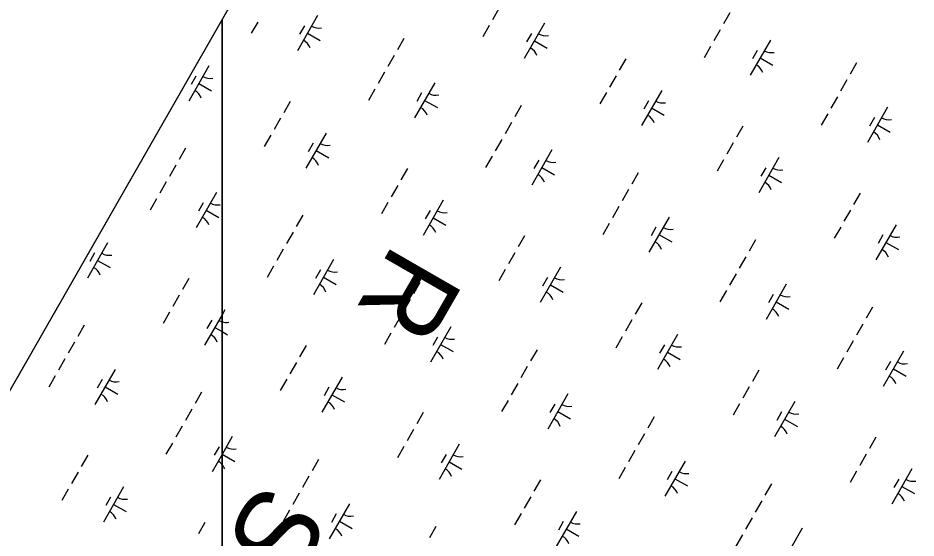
# Model space of a CAD drawing. Extents: x 3930721 to 3950824, y 220441 to 242861.
# Drawn here: x 3937829 to 3938935, y 232817 to 233458 of the extents above; entities that cross this region are included whole.
import ezdxf

# ---------------------------------------------------------------- set-up
doc = ezdxf.new("R2010")
doc.units = 0
for name, color, linetype in [('V-GRID-FRAM', 7, 'Continuous'), ('V-RIVR-IDEN', 7, 'Continuous'), ('V-WETL-SWMP', 7, 'Continuous')]:
    doc.layers.add(name, color=color, linetype=linetype)

msp = doc.modelspace()

# ---------------------------------------------------------------- linework, layer by layer
at = {"layer": 'V-GRID-FRAM'}
msp.add_lwpolyline([(3948829, 235080.9), (3941569.4, 222286.8), (3934009.8, 226348.1), (3941449.6, 239338.6), (3948829, 235080.9)], dxfattribs=at)
at = {"layer": 'V-WETL-SWMP'}
for p, q in [((3938287.6, 233817.5), (3938080.4, 233455.6)), ((3938421.5, 233469.2), (3938413.5, 233455.3)), ((3938706, 233464), (3938698, 233450.2)), ((3938080.4, 233455.6), (3937727.7, 232839.8)), ((3938080.4, 233455.6), (3938080.4, 228590.6)), ((3938080.4, 228590.6), (3938080.4, 233455.6)), ((3938124.4, 233452.6), (3938116.4, 233438.7)), ((3938198.1, 233460.6), (3938173.3, 233417.2)), ((3938182, 233447.9), (3938176, 233437.5)), ((3938409.5, 233448.3), (3938401.6, 233434.4)), ((3938477.7, 233451.1), (3938452.8, 233407.8)), ((3938694, 233443.2), (3938686.1, 233429.3)), ((3938185.7, 233438.9), (3938201.3, 233430)), ((3938304.5, 233432.4), (3938296.6, 233418.5)), ((3938461.5, 233438.5), (3938455.6, 233428.1)), ((3938755.9, 233430.4), (3938731, 233387)), ((3938465.2, 233429.4), (3938480.9, 233420.5)), ((3938682.1, 233422.4), (3938674.2, 233408.5)), ((3938292.6, 233411.6), (3938284.6, 233397.7)), ((3938739.7, 233417.7), (3938733.8, 233407.3)), ((3938743.5, 233408.7), (3938759.1, 233399.7)), ((3938064.3, 233398.7), (3938039.4, 233355.3)), ((3938577.7, 233407.3), (3938569.8, 233393.4)), ((3938862.2, 233402.2), (3938854.3, 233388.3)), ((3938048.1, 233386.1), (3938042.2, 233375.6)), ((3938280.6, 233390.8), (3938272.7, 233376.9)), ((3938565.8, 233386.5), (3938557.9, 233372.6)), ((3938051.8, 233377), (3938067.5, 233368.1)), ((3938342.5, 233377.9), (3938317.6, 233334.5)), ((3938850.3, 233381.4), (3938842.4, 233367.5)), ((3938268.7, 233370), (3938260.8, 233356.1)), ((3938326.3, 233365.3), (3938320.4, 233354.9)), ((3938553.9, 233365.7), (3938545.9, 233351.8)), ((3938622, 233368.5), (3938597.2, 233325.1)), ((3938164.3, 233354.9), (3938156.4, 233341)), ((3938330, 233356.2), (3938345.7, 233347.3)), ((3938605.9, 233355.8), (3938599.9, 233345.4)), ((3938838.4, 233360.5), (3938830.4, 233346.7)), ((3938448.8, 233349.8), (3938440.9, 233335.9)), ((3938609.6, 233346.8), (3938625.2, 233337.8)), ((3938900.2, 233347.7), (3938875.4, 233304.3)), ((3938152.4, 233334.1), (3938144.5, 233320.2)), ((3938826.5, 233339.7), (3938818.5, 233325.8)), ((3938884.1, 233335), (3938878.1, 233324.6)), ((3938436.9, 233328.9), (3938429, 233315.1)), ((3938722.1, 233324.6), (3938714.1, 233310.8)), ((3938887.8, 233326), (3938903.4, 233317.1)), ((3938140.5, 233313.2), (3938132.5, 233299.3)), ((3938208.6, 233316), (3938183.8, 233272.7)), ((3938035.4, 233297.3), (3938027.5, 233283.4)), ((3938192.5, 233303.4), (3938186.5, 233293)), ((3938425, 233308.1), (3938417, 233294.2)), ((3938710.2, 233303.8), (3938702.2, 233289.9)), ((3938196.2, 233294.3), (3938211.8, 233285.4)), ((3938413.1, 233287.3), (3938405.1, 233273.4)), ((3938486.8, 233295.3), (3938462, 233251.9)), ((3938023.5, 233276.5), (3938015.6, 233262.6)), ((3938470.7, 233282.6), (3938464.7, 233272.2)), ((3938698.2, 233283), (3938690.3, 233269.1)), ((3938766.3, 233285.8), (3938741.5, 233242.4)), ((3938308.7, 233272.2), (3938300.7, 233258.3)), ((3938474.4, 233273.6), (3938490, 233264.6)), ((3938593.2, 233267.1), (3938585.2, 233253.2)), ((3938750.2, 233273.2), (3938744.2, 233262.7)), ((3938753.9, 233264.1), (3938769.5, 233255.2)), ((3938011.6, 233255.7), (3938003.6, 233241.8)), ((3938073.4, 233242.8), (3938048.6, 233199.4)), ((3938296.8, 233251.4), (3938288.8, 233237.5)), ((3938581.3, 233246.3), (3938573.3, 233232.4)), ((3938866.4, 233242), (3938858.5, 233228.1)), ((3937999.7, 233234.8), (3937991.7, 233221)), ((3938352.9, 233233.4), (3938328.1, 233190)), ((3938057.3, 233230.2), (3938051.3, 233219.8)), ((3938061, 233221.1), (3938076.6, 233212.2)), ((3938284.8, 233230.6), (3938276.9, 233216.7)), ((3938336.8, 233220.7), (3938330.8, 233210.3)), ((3938569.3, 233225.4), (3938561.4, 233211.6)), ((3938854.5, 233221.2), (3938846.5, 233207.3)), ((3938179.8, 233214.7), (3938171.8, 233200.8)), ((3938340.5, 233211.7), (3938356.1, 233202.7)), ((3938631.2, 233212.6), (3938606.3, 233169.2)), ((3938557.4, 233204.6), (3938549.5, 233190.7)), ((3938615, 233199.9), (3938609.1, 233189.5)), ((3938842.6, 233200.3), (3938834.6, 233186.4)), ((3938910.7, 233203.1), (3938885.8, 233159.8)), ((3938167.9, 233193.8), (3938159.9, 233180)), ((3938453, 233189.5), (3938445.1, 233175.7)), ((3938618.7, 233190.9), (3938634.4, 233182)), ((3938894.6, 233190.5), (3938888.6, 233180.1)), ((3937939.5, 233180.9), (3937914.7, 233137.5)), ((3938737.5, 233184.4), (3938729.6, 233170.5)), ((3938898.3, 233181.4), (3938913.9, 233172.5)), ((3937923.4, 233168.3), (3937917.4, 233157.9)), ((3938155.9, 233173), (3938148, 233159.1)), ((3938441.1, 233168.7), (3938433.1, 233154.8)), ((3937927.1, 233159.2), (3937942.7, 233150.3)), ((3938217.8, 233160.2), (3938192.9, 233116.8)), ((3938725.6, 233163.6), (3938717.6, 233149.7)), ((3938144, 233152.2), (3938136, 233138.3)), ((3938201.6, 233147.5), (3938195.7, 233137.1)), ((3938429.2, 233147.9), (3938421.2, 233134)), ((3938497.3, 233150.7), (3938472.4, 233107.3)), ((3938713.7, 233142.8), (3938705.7, 233128.9)), ((3938039.6, 233137.1), (3938031.7, 233123.2)), ((3938205.3, 233138.5), (3938221, 233129.5)), ((3938324.1, 233132), (3938316.2, 233118.1)), ((3938481.2, 233138.1), (3938475.2, 233127.6)), ((3938484.9, 233129), (3938500.5, 233120.1)), ((3938701.7, 233122), (3938693.8, 233108.1)), ((3938775.5, 233129.9), (3938750.6, 233086.5)), ((3938027.7, 233116.3), (3938019.7, 233102.4)), ((3938312.2, 233111.2), (3938304.2, 233097.3)), ((3938759.4, 233117.3), (3938753.4, 233106.9)), ((3938083.9, 233098.3), (3938080.4, 233092.1)), ((3938597.4, 233106.9), (3938589.4, 233093)), ((3938763.1, 233108.2), (3938778.7, 233099.3)), ((3938881.9, 233101.8), (3938873.9, 233087.9)), ((3938015.8, 233095.5), (3938007.8, 233081.6)), ((3938080.4, 233092.1), (3938059, 233054.9)), ((3938300.3, 233090.3), (3938292.3, 233076.5)), ((3937910.7, 233079.6), (3937902.8, 233065.7)), ((3938067.7, 233085.6), (3938061.8, 233075.2)), ((3938071.5, 233076.6), (3938080.4, 233071.5)), ((3938362.1, 233077.5), (3938337.2, 233034.1)), ((3938585.4, 233086.1), (3938577.5, 233072.2)), ((3938869.9, 233080.9), (3938862, 233067.1)), ((3938080.4, 233071.5), (3938087.1, 233067.6)), ((3938288.3, 233069.5), (3938280.4, 233055.6)), ((3938346, 233064.8), (3938340, 233054.4)), ((3938573.5, 233065.2), (3938565.6, 233051.3)), ((3938641.6, 233068), (3938616.8, 233024.7)), ((3937898.8, 233058.7), (3937890.8, 233044.8)), ((3938184, 233054.4), (3938176, 233040.6)), ((3938349.7, 233055.8), (3938365.3, 233046.9)), ((3938625.5, 233055.4), (3938619.5, 233045)), ((3938858, 233060.1), (3938850.1, 233046.2)), ((3938468.5, 233049.3), (3938460.5, 233035.4)), ((3938629.2, 233046.3), (3938644.8, 233037.4)), ((3938919.8, 233047.3), (3938895, 233003.9)), ((3937886.9, 233037.9), (3937878.9, 233024)), ((3938172, 233033.6), (3938164.1, 233019.7)), ((3938846.1, 233039.3), (3938838.1, 233025.4)), ((3938903.7, 233034.6), (3938897.7, 233024.2)), ((3937948.7, 233025.1), (3937923.8, 232981.7)), ((3938456.5, 233028.5), (3938448.6, 233014.6)), ((3938741.7, 233024.2), (3938733.8, 233010.3)), ((3938907.4, 233025.6), (3938923, 233016.6)), ((3937874.9, 233017.1), (3937867, 233003.2)), ((3937932.6, 233012.4), (3937926.6, 233002)), ((3938160.1, 233012.8), (3938152.2, 232998.9)), ((3938228.2, 233015.6), (3938203.4, 232972.2)), ((3937936.3, 233003.4), (3937951.9, 232994.4)), ((3938212.1, 233003), (3938206.1, 232992.5)), ((3938444.6, 233007.7), (3938436.7, 232993.8)), ((3938729.8, 233003.4), (3938721.8, 232989.5)), ((3938055.1, 232996.9), (3938047.1, 232983)), ((3938215.8, 232993.9), (3938231.4, 232985)), ((3938506.4, 232994.8), (3938481.6, 232951.4)), ((3938432.7, 232986.9), (3938424.7, 232973)), ((3938490.3, 232982.2), (3938484.3, 232971.8)), ((3938717.9, 232982.6), (3938709.9, 232968.7)), ((3938786, 232985.4), (3938761.1, 232942)), ((3938043.1, 232976.1), (3938035.2, 232962.2)), ((3938328.3, 232971.8), (3938320.4, 232957.9)), ((3938494, 232973.1), (3938509.6, 232964.2)), ((3938612.8, 232966.7), (3938604.9, 232952.8)), ((3938769.8, 232972.7), (3938763.9, 232962.3)), ((3938031.2, 232955.2), (3938023.3, 232941.4)), ((3938773.5, 232963.7), (3938789.2, 232954.7)), ((3938316.4, 232951), (3938308.4, 232937.1)), ((3938600.9, 232945.8), (3938592.9, 232932)), ((3938019.3, 232934.4), (3938011.3, 232920.5)), ((3938093, 232942.4), (3938080.4, 232920.3)), ((3938372.6, 232932.9), (3938347.7, 232889.5)), ((3938886, 232941.5), (3938878.1, 232927.7)), ((3938076.9, 232929.7), (3938070.9, 232919.3)), ((3938304.4, 232930.1), (3938296.5, 232916.2)), ((3938589, 232925), (3938581, 232911.1)), ((3937914.9, 232919.3), (3937906.9, 232905.5)), ((3938080.4, 232920.3), (3938068.2, 232899)), ((3938080.6, 232920.7), (3938096.2, 232911.8)), ((3938199.4, 232914.2), (3938191.5, 232900.3)), ((3938356.4, 232920.3), (3938350.5, 232909.9)), ((3938360.1, 232911.2), (3938375.8, 232902.3)), ((3938650.8, 232912.2), (3938625.9, 232868.8)), ((3938874.1, 232920.7), (3938866.2, 232906.8)), ((3938577, 232904.2), (3938569.1, 232890.3)), ((3938634.6, 232899.5), (3938628.7, 232889.1)), ((3938862.2, 232899.9), (3938854.2, 232886)), ((3938930.3, 232902.7), (3938905.5, 232859.3)), ((3937903, 232898.5), (3937895, 232884.6)), ((3938187.5, 232893.4), (3938179.5, 232879.5)), ((3938472.6, 232889.1), (3938464.7, 232875.2)), ((3938638.4, 232890.5), (3938654, 232881.5)), ((3938914.2, 232890.1), (3938908.2, 232879.6)), ((3937891, 232877.7), (3937883.1, 232863.8)), ((3937959.2, 232880.5), (3937934.3, 232837.1)), ((3938757.1, 232884), (3938749.2, 232870.1)), ((3938917.9, 232881), (3938933.5, 232872.1)), ((3937943, 232867.8), (3937937.1, 232857.4)), ((3938175.6, 232872.6), (3938167.6, 232858.7)), ((3938460.7, 232868.3), (3938452.8, 232854.4)), ((3937946.7, 232858.8), (3937962.4, 232849.9)), ((3938237.4, 232859.7), (3938212.5, 232816.3)), ((3938745.2, 232863.2), (3938737.3, 232849.3)), ((3938163.6, 232851.7), (3938155.7, 232837.9)), ((3938221.2, 232847.1), (3938215.3, 232836.7)), ((3938448.8, 232847.5), (3938440.8, 232833.6)), ((3938516.9, 232850.3), (3938492.1, 232806.9)), ((3938059.2, 232836.7), (3938051.3, 232822.8)), ((3938225, 232838), (3938240.6, 232829.1)), ((3938500.8, 232837.6), (3938494.8, 232827.2)), ((3938733.3, 232842.3), (3938725.3, 232828.5)), ((3938343.7, 232831.6), (3938335.8, 232817.7)), ((3938504.5, 232828.6), (3938520.1, 232819.6)), ((3938721.4, 232821.5), (3938713.4, 232807.6)), ((3938795.1, 232829.5), (3938770.3, 232786.1))]:
    msp.add_line(p, q, dxfattribs=at)
for centre, start, end in [((3938199.6, 233462.8), 239.4279, 280.9715), ((3938172.2, 233414.8), 19.4279, 60.9715), ((3938479.2, 233453.3), 239.4279, 280.9715), ((3938451.7, 233405.4), 19.4279, 60.9715), ((3938757.4, 233432.5), 239.4279, 280.9715), ((3938729.9, 233384.6), 19.4279, 60.9715), ((3938065.8, 233400.9), 239.4279, 280.9715), ((3938038.3, 233352.9), 19.4279, 60.9715), ((3938344, 233380.1), 239.4279, 280.9715), ((3938623.5, 233370.6), 239.4279, 280.9715), ((3938316.5, 233332.1), 19.4279, 60.9715), ((3938596.1, 233322.7), 19.4279, 60.9715), ((3938901.7, 233349.9), 239.4279, 280.9715), ((3938874.3, 233301.9), 19.4279, 60.9715), ((3938210.1, 233318.2), 239.4279, 280.9715), ((3938182.7, 233270.3), 19.4279, 60.9715), ((3938488.3, 233297.4), 239.4279, 280.9715), ((3938460.9, 233249.5), 19.4279, 60.9715), ((3938767.9, 233288), 239.4279, 280.9715), ((3938740.4, 233240), 19.4279, 60.9715), ((3938074.9, 233245), 239.4279, 280.9715), ((3938354.5, 233235.5), 239.4279, 280.9715), ((3938047.5, 233197), 19.4279, 60.9715), ((3938327, 233187.6), 19.4279, 60.9715), ((3938632.7, 233214.8), 239.4279, 280.9715), ((3938912.2, 233205.3), 239.4279, 280.9715), ((3938605.2, 233166.8), 19.4279, 60.9715), ((3937941.1, 233183.1), 239.4279, 280.9715), ((3938884.7, 233157.4), 19.4279, 60.9715), ((3937913.6, 233135.2), 19.4279, 60.9715), ((3938219.3, 233162.3), 239.4279, 280.9715), ((3938498.8, 233152.9), 239.4279, 280.9715), ((3938191.8, 233114.4), 19.4279, 60.9715), ((3938471.3, 233104.9), 19.4279, 60.9715), ((3938777, 233132.1), 239.4279, 280.9715), ((3938749.6, 233084.2), 19.4279, 60.9715), ((3938085.4, 233100.4), 239.4279, 253.415), ((3938085.4, 233100.4), 253.415, 280.9715), ((3938057.9, 233052.5), 19.4279, 60.9715), ((3938363.6, 233079.7), 239.4279, 280.9715), ((3938643.1, 233070.2), 239.4279, 280.9715), ((3938336.2, 233031.7), 19.4279, 60.9715), ((3938615.7, 233022.3), 19.4279, 60.9715), ((3938921.3, 233049.4), 239.4279, 280.9715), ((3937950.2, 233027.2), 239.4279, 280.9715), ((3938893.9, 233001.5), 19.4279, 60.9715), ((3938229.7, 233017.8), 239.4279, 280.9715), ((3937922.7, 232979.3), 19.4279, 60.9715), ((3938202.3, 232969.8), 19.4279, 60.9715), ((3938507.9, 232997), 239.4279, 280.9715), ((3938787.5, 232987.5), 239.4279, 280.9715), ((3938480.5, 232949), 19.4279, 60.9715), ((3938760, 232939.6), 19.4279, 60.9715), ((3938094.5, 232944.5), 239.4279, 280.9715), ((3938067.1, 232896.6), 41.1221, 60.9715), ((3938374.1, 232935.1), 239.4279, 280.9715), ((3938067.1, 232896.6), 19.4279, 41.1221), ((3938346.6, 232887.2), 19.4279, 60.9715), ((3938652.3, 232914.3), 239.4279, 280.9715), ((3938931.8, 232904.9), 239.4279, 280.9715), ((3938624.8, 232866.4), 19.4279, 60.9715), ((3937960.7, 232882.7), 239.4279, 280.9715), ((3938904.4, 232856.9), 19.4279, 60.9715), ((3937933.2, 232834.7), 19.4279, 60.9715), ((3938238.9, 232861.9), 239.4279, 280.9715), ((3938518.4, 232852.4), 239.4279, 280.9715), ((3938211.4, 232813.9), 19.4279, 60.9715), ((3938491, 232804.5), 19.4279, 60.9715)]:
    msp.add_arc(centre, 17.6, start, end, dxfattribs=at)

# ---------------------------------------------------------------- texts
at = {"layer": 'V-RIVR-IDEN'}
for s, rotation, p in [(' R   ', 240.1031, (3938310.9, 233214.4)), ('S  I   D  E', 240.1015, (3938127.8, 232889.5))]:
    msp.add_text(s, height=100, rotation=rotation, dxfattribs=at).set_placement(p)

doc.saveas('drawing.dxf')
